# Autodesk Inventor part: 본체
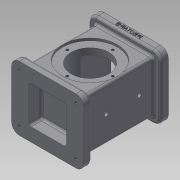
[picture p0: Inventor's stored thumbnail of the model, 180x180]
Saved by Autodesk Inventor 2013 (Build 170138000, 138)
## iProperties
Created: 2017-08
Part Number: 본체
Material: Generic
Document SubType Name: Modeling
Designer: Administrator
Density: 1 g/cm^3
Author: Administrator
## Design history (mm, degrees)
sketch "스케치1"
  geometry: L1 (-36, 41)-(36, 41); L2 (46, 31)-(46, -31); L3 (36, -41)-(-36, -41); L4 (-46, -31)-(-46, 31); A1 r 10 centre (36, 31) between (46, 31) and (36, 41); A2 r 10 centre (-36, 31) between (-36, 41) and (-46, 31); A3 r 10 centre (-36, -31) between (-46, -31) and (-36, -41); A4 r 10 centre (36, -31) between (36, -41) and (46, -31); 6 further points
  constraints: 8 end point, 8 point on circle, 8 tangent, 6 point on line, 4 centre point, 3 equal radius, 2 midpoint, 2 parallel, 1 horizontal, 1 horizontal alignment, 1 perpendicular, 1 vertical alignment
  dimensions: "d0" = 92 distance of point (-46, 41) point (46, 41); "d2" = 82 distance of point (46, 41) point (46, -41); "d3" = 10 radius of A1
extrude "돌출1" new body sketch "스케치1" distance "d4" = 10; taper "d5" = 0 deg
sketch "스케치2"
  geometry: L1 (-36, 41)-(36, 41) reference; L2 (36, -41)-(-36, -41) reference; L3 (46, 31)-(46, -31) reference; L4 (-37, 0)-(-37, 30); L5 (-34, 33)-(34, 33); L6 (37, 30)-(37, -30); L7 (34, -33)-(-34, -33); L8 (-37, -30)-(-37, 0); A1 r 3 centre (-34, 30) between (-34, 33) and (-37, 30); A2 r 3 centre (34, 30) between (37, 30) and (34, 33); A3 r 3 centre (34, -30) between (34, -33) and (37, -30); A4 r 3 centre (-34, -30) between (-37, -30) and (-34, -33); 5 further points
  constraints: 10 end point, 8 point on circle, 8 point on line, 8 tangent, 4 centre point, 3 equal radius, 2 perpendicular, 1 parallel
  dimensions: "d11" = 33 distance of L4.start point (-37, 33); "d12" = 74 distance of point (-37, 33) point (37, 33); "d13" = 66 distance of point (37, 33) point (37, -33); "d14" = 74 distance of point (37, -33) point (-37, -33); "d15" = 33 distance of point (-37, -33) L4.start (derived); "d16" = 3 radius of A1; "d17" = 71 distance of L5.start point (37, 33); "d18" = 9 distance between parallel lines of L3 L6; "d19" = 74 distance between parallel lines of L2 L5
extrude "돌출2" join sketch "스케치2" distance "d20" = 88; taper "d21" = 0 deg
sketch "스케치3"
  geometry: L1 (-46, 0)-(-46, 31); L2 (-36, 41)-(36, 41); L3 (46, 31)-(46, -31); L4 (36, -41)-(-36, -41); L5 (-46, -31)-(-46, 0); A1 r 10 centre (-36, 31) between (-36, 41) and (-46, 31); A2 r 10 centre (36, 31) between (46, 31) and (36, 41); A3 r 10 centre (36, -31) between (36, -41) and (46, -31); A4 r 10 centre (-36, -31) between (-46, -31) and (-36, -41); 5 further points
  constraints: 10 end point, 9 tangent, 8 point on circle, 8 point on line, 4 centre point, 3 equal radius, 1 parallel
  dimensions: "d23" = 41 distance of L1.start point (-46, 41); "d24" = 92 distance of point (-46, 41) point (46, 41); "d25" = 82 distance of point (46, 41) point (46, -41); "d26" = 92 distance of point (46, -41) point (-46, -41); "d27" = 41 distance of point (-46, -41) L1.start (derived); "d28" = 10 radius of A1
extrude "돌출3" join sketch "스케치3" distance "d31" = 10; taper "d32" = 0 deg
sketch "스케치4"
  geometry: L1 (0, 0)-(68, 0) reference; C1 r 24 at (34, -44); 1 further point
  constraints: 1 centre point
  dimensions: "d34" = 48 diameter of C1; "d35" = 44 distance from line of C1.centre L1; "d36" = 55.60576 distance of L1.end C1.centre
extrude "돌출4" cut sketch "스케치4" distance "d37" = 68; taper "d38" = 0 deg
sketch "스케치5"
  geometry: C1 r 24 at (34, -44) reference; C2 r 35 at (34, -44); 1 further point
  constraints: 1 centre point, 1 coincident
  dimensions: "d39" = 70 diameter of C2
extrude "돌출5" cut sketch "스케치5" distance "d40" = 3; taper "d41" = 0 deg
sketch "스케치6"
  geometry: L1 (-46, 31)-(-46, -31) reference; L2 (46, -31)-(46, 31) reference; L3 (36, 41)-(-36, 41) reference; L4 (-24, 0)-(-24, 21); L5 (-21, 24)-(21, 24); L6 (24, 21)-(24, -21); L7 (21, -24)-(-21, -24); L8 (-24, -21)-(-24, 0); A1 r 3 centre (-21, 21) between (-21, 24) and (-24, 21); A2 r 3 centre (21, 21) between (24, 21) and (21, 24); A3 r 3 centre (21, -21) between (21, -24) and (24, -21); A4 r 3 centre (-21, -21) between (-24, -21) and (-21, -24); 5 further points
  constraints: 10 end point, 9 tangent, 8 point on circle, 8 point on line, 4 centre point, 3 equal radius, 2 parallel, 1 perpendicular
  dimensions: "d46" = 24 distance of L4.start point (-24, 24); "d47" = 48 distance of point (-24, 24) point (24, 24); "d48" = 48 distance of point (24, 24) point (24, -24); "d49" = 48 distance of point (24, -24) point (-24, -24); "d50" = 24 distance of point (-24, -24) L4.start (derived); "d51" = 3 radius of A1; "d52" = 65 distance between parallel lines of L3 L7; "d53" = 70 distance between parallel lines of L8 L2
extrude "돌출6" cut sketch "스케치6" distance "d54" = 16; taper "d55" = 0 deg
sketch "스케치7"
  geometry: L1 (-22, 0)-(-22, 19); L2 (-19, 22)-(19, 22); L3 (22, 19)-(22, -19); L4 (19, -22)-(-19, -22); L5 (-22, -19)-(-22, 0); A1 r 3 centre (-19, 19) between (-19, 22) and (-22, 19); A2 r 3 centre (19, 19) between (22, 19) and (19, 22); A3 r 3 centre (19, -19) between (19, -22) and (22, -19); A4 r 3 centre (-19, -19) between (-22, -19) and (-19, -22); 5 further points
  constraints: 10 end point, 8 point on circle, 8 point on line, 8 tangent, 4 centre point, 3 equal radius, 1 parallel
  dimensions: "d57" = 22 distance of L1.start point (-22, 22); "d58" = 44 distance of point (-22, 22) point (22, 22); "d59" = 44 distance of point (22, 22) point (22, -22); "d60" = 44 distance of point (22, -22) point (-22, -22); "d61" = 22 distance of point (-22, -22) L1.start (derived); "d62" = 3 radius of A1
extrude "돌출7" cut sketch "스케치7" distance "d63" = 82; taper "d64" = 0 deg
sketch "스케치8"
  geometry: L1 (-26.39, 0)-(-26.39, 26); L2 (-26.39, 26)-(25.61, 26); L3 (25.61, 26)-(25.61, -26); L4 (25.61, -26)-(-26.39, -26); L5 (-26.39, -26)-(-26.39, 0); 1 further point
  constraints: 10 end point, 1 perpendicular
  dimensions: "d67" = 26 distance of L1.start L1.end; "d68" = 52 distance of L1.end L2.end; "d69" = 52 distance of L2.end L3.end; "d70" = 52 distance of L3.end L4.end; "d71" = 26 distance of L4.end L1.start (derived)
extrude "돌출8" cut sketch "스케치8" distance "d72" = 8; taper "d73" = 0 deg
sketch "스케치9"
  geometry: 2 further points
hole "구멍1" sketch "스케치9" at (0, 29) diameter "d75" = 3.242; stored, may be unused: countersink angle "d79" = 90 deg, drill point angle "d81" = 118 deg; dims "d76" = 4, "d77" = 4, "d78" = 2, "d80" = 6
sketch "스케치10"
  geometry: 5 further points
hole "구멍2" sketch "스케치10" at (-36, 31), (36, 31), (36, -31), (-36, -31) diameter "d87" = 3.242; stored, may be unused: countersink angle "d91" = 90 deg, drill point angle "d93" = 118 deg; dims "d88" = 4, "d89" = 4, "d90" = 2, "d92" = 6
node "작업 평면1"
sketch "스케치11"
  geometry: C1 r 2.5 at (30, -18); C2 r 2.5 at (30, -60); 1 further point
  constraints: 2 centre point
  dimensions: "d99" = 5 diameter of C1; "d100" = 5 diameter of C2; "d101" = 18 distance of point (30, 0) C1.centre; "d102" = 60 distance of point (30, 0) C2.centre; "d103" = 42 distance of C1.centre C2.centre
extrude "돌출9" cut sketch "스케치11" stored distance "d104" = 8; taper "d105" = 0 deg
sketch "스케치13"
  geometry: 2 further points
  constraints: 1 other
feature "엠보싱1" sketch "스케치13" dims "d0" = 92, "d2" = 82, "d3" = 10, "d109" = 0.5, "d110" = 0
fillet "모깎기1" dims "d111" = 3
chamfer "모따기1" distance "d112" = 1; stored, may be unused: second distance "d113" = 2, angle "d114" = 45 deg
chamfer "모따기2" distance "d115" = 1; stored, may be unused: second distance "d116" = 2, angle "d117" = 45 deg
chamfer "모따기3" distance "d118" = 1; stored, may be unused: second distance "d119" = 2, angle "d120" = 45 deg
chamfer "모따기4" distance "d121" = 1; stored, may be unused: second distance "d122" = 2, angle "d123" = 45 deg
node "솔리드1"
mirror "대칭1"
pattern_circular "원형 패턴1" dims angle "d83" = 360 deg
mirror "대칭2"
mirror "대칭3"
other parameters: "d94" = -54
